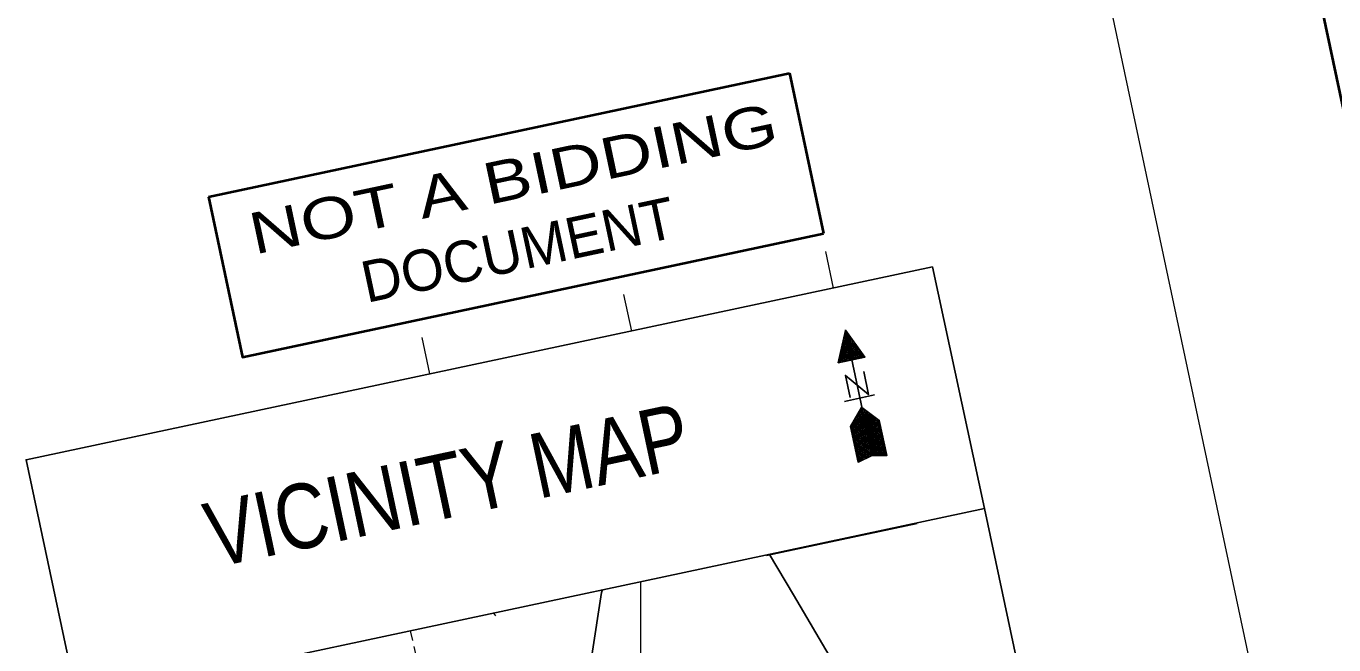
# Model space of a CAD drawing. Extents: x 2357218 to 2371708, y 6973728 to 6980157.
# Drawn here: x 2357218 to 2357852, y 6974891 to 6975190 of the extents above; entities that cross this region are included whole.
import ezdxf
from ezdxf.enums import TextEntityAlignment as Align

# ---------------------------------------------------------------- set-up
doc = ezdxf.new("R2010")
doc.units = 0
doc.header["$LTSCALE"] = 2
doc.linetypes.add('MEDIUM_DASHED', pattern=[4.5, 3, -1.5])
for name, color, linetype, lineweight in [('44', 7, 'Continuous', 13), ('62', 7, 'Continuous', 13), ('63', 7, 'Continuous', 13)]:
    doc.layers.add(name, color=color, linetype=linetype, lineweight=lineweight)

msp = doc.modelspace()

# ---------------------------------------------------------------- linework, layer by layer
at = {"layer": '44'}
msp.add_line((2358039.664, 6973807.926), (2357291.149, 6977329.415), dxfattribs=at)
at = {"layer": '44', "lineweight": 40}
msp.add_lwpolyline([(2358116.692, 6973926.537), (2357409.76, 6977252.388), (2370517.53, 6980038.532)], dxfattribs=at)
at = {"layer": '62', "lineweight": 40}
for p, q in [((2357306.373, 6975107.636), (2357588.056, 6975167.509)), ((2357588.056, 6975167.509), (2357604.573, 6975089.803))]:
    msp.add_line(p, q, dxfattribs=at)
at = {"layer": '62'}
for p, q in [((2357605.468, 6975081.127), (2357609.235, 6975063.405)), ((2357507.65, 6975060.335), (2357511.417, 6975042.612)), ((2357614.522, 6975039.726), (2357617.208, 6975040.297)), ((2357614.683, 6975040.382), (2357616.819, 6975040.837)), ((2357617.301, 6975028.402), (2357614.717, 6975040.55)), ((2357614.833, 6975041.083), (2357616.418, 6975041.417)), ((2357614.994, 6975041.737), (2357616.006, 6975041.951)), ((2357617.915, 6975028.532), (2357615.052, 6975042.001)), ((2357615.149, 6975042.414), (2357615.611, 6975042.512)), ((2357618.532, 6975028.663), (2357615.575, 6975042.572)), ((2357619.147, 6975028.797), (2357616.491, 6975041.295)), ((2357409.831, 6975039.543), (2357413.598, 6975021.82)), ((2357612.86, 6975032.288), (2357621.62, 6975034.152)), ((2357613.036, 6975032.972), (2357621.225, 6975034.712)), ((2357613.171, 6975033.644), (2357620.83, 6975035.272)), ((2357613.325, 6975034.321), (2357620.435, 6975035.833)), ((2357614.832, 6975027.877), (2357613.396, 6975034.635)), ((2357613.48, 6975034.998), (2357620.018, 6975036.388)), ((2357613.614, 6975035.669), (2357619.623, 6975036.948)), ((2357615.448, 6975028.008), (2357613.722, 6975036.129)), ((2357613.768, 6975036.346), (2357619.206, 6975037.504)), ((2357613.922, 6975037.025), (2357618.811, 6975038.064)), ((2357616.064, 6975028.14), (2357614.053, 6975037.602)), ((2357614.079, 6975037.7), (2357618.393, 6975038.619)), ((2357614.239, 6975038.355), (2357618.002, 6975039.157)), ((2357614.388, 6975039.056), (2357617.604, 6975039.739)), ((2357616.681, 6975028.271), (2357614.388, 6975039.056)), ((2357619.743, 6975028.921), (2357617.385, 6975040.014)), ((2357620.38, 6975029.057), (2357618.317, 6975038.763)), ((2357620.996, 6975029.188), (2357619.233, 6975037.486)), ((2357621.589, 6975029.313), (2357620.122, 6975036.226)), ((2357622.229, 6975029.449), (2357621.059, 6975034.951)), ((2357611.814, 6975027.58), (2357624.426, 6975030.263)), ((2357611.973, 6975028.235), (2357624.035, 6975030.801)), ((2357612.367, 6975027.354), (2357612.075, 6975028.739)), ((2357612.127, 6975028.914), (2357623.64, 6975031.361)), ((2357612.258, 6975029.609), (2357623.219, 6975031.938)), ((2357612.983, 6975027.485), (2357612.401, 6975030.236)), ((2357612.415, 6975030.264), (2357622.827, 6975032.475)), ((2357612.572, 6975030.939), (2357622.432, 6975033.035)), ((2357612.705, 6975031.611), (2357622.015, 6975033.592)), ((2357613.601, 6975027.616), (2357612.734, 6975031.688)), ((2357614.216, 6975027.747), (2357613.06, 6975033.183)), ((2357622.823, 6975029.577), (2357621.953, 6975033.671)), ((2357623.44, 6975029.707), (2357622.864, 6975032.415)), ((2357624.077, 6975029.843), (2357623.801, 6975031.142)), ((2357611.772, 6975027.228), (2357611.758, 6975027.294)), ((2357620.457, 6975001.098), (2357627.168, 6975002.527)), ((2357620.875, 6975001.833), (2357626.488, 6975003.026)), ((2357621.311, 6975002.59), (2357625.824, 6975003.552)), ((2357626.004, 6974981.388), (2357621.445, 6975002.827)), ((2357621.736, 6975003.302), (2357625.148, 6975004.03)), ((2357626.585, 6974981.674), (2357621.914, 6975003.641)), ((2357622.155, 6975004.037), (2357624.489, 6975004.532)), ((2357627.177, 6974981.937), (2357622.391, 6975004.456)), ((2357622.576, 6975004.769), (2357623.808, 6975005.033)), ((2357627.759, 6974982.222), (2357622.861, 6975005.267)), ((2357628.38, 6974982.331), (2357623.505, 6975005.267)), ((2357629.024, 6974982.33), (2357624.271, 6975004.692)), ((2357629.647, 6974982.323), (2357625.015, 6975004.116)), ((2357630.319, 6974982.306), (2357625.798, 6975003.569)), ((2357630.959, 6974982.327), (2357626.564, 6975002.995)), ((2357631.585, 6974982.298), (2357627.303, 6975002.44)), ((2357621.331, 6974979.131), (2357617.675, 6974996.321)), ((2357617.715, 6974996.029), (2357631.649, 6974998.993)), ((2357617.845, 6974995.415), (2357631.78, 6974998.377)), ((2357617.914, 6974996.716), (2357631.207, 6974999.543)), ((2357617.976, 6974994.799), (2357631.909, 6974997.76)), ((2357618.108, 6974994.18), (2357632.04, 6974997.142)), ((2357621.934, 6974979.419), (2357618.168, 6974997.14)), ((2357618.239, 6974993.564), (2357632.172, 6974996.525)), ((2357618.316, 6974997.425), (2357630.529, 6975000.021)), ((2357618.37, 6974992.946), (2357632.305, 6974995.909)), ((2357622.498, 6974979.701), (2357618.618, 6974997.947)), ((2357618.751, 6974998.184), (2357629.867, 6975000.547)), ((2357623.08, 6974979.984), (2357619.087, 6974998.761)), ((2357619.17, 6974998.917), (2357629.186, 6975001.046)), ((2357623.663, 6974980.27), (2357619.56, 6974999.573)), ((2357619.617, 6974999.634), (2357628.511, 6975001.522)), ((2357620.031, 6975000.388), (2357627.847, 6975002.047)), ((2357624.252, 6974980.532), (2357620.031, 6975000.388)), ((2357624.835, 6974980.817), (2357620.502, 6975001.202)), ((2357625.418, 6974981.103), (2357620.973, 6975002.015)), ((2357632.248, 6974982.303), (2357628.091, 6975001.871)), ((2357632.873, 6974982.297), (2357628.835, 6975001.293)), ((2357633.517, 6974982.298), (2357629.601, 6975000.72)), ((2357634.183, 6974982.299), (2357630.389, 6975000.151)), ((2357634.806, 6974982.295), (2357631.128, 6974999.596)), ((2357618.501, 6974992.33), (2357632.434, 6974995.292)), ((2357618.632, 6974991.715), (2357632.565, 6974994.675)), ((2357618.761, 6974991.098), (2357632.696, 6974994.06)), ((2357618.892, 6974990.481), (2357632.825, 6974993.443)), ((2357619.027, 6974989.866), (2357632.958, 6974992.826)), ((2357619.153, 6974989.273), (2357633.084, 6974992.232)), ((2357619.287, 6974988.633), (2357633.221, 6974991.595)), ((2357619.418, 6974988.017), (2357633.35, 6974990.979)), ((2357619.546, 6974987.422), (2357633.479, 6974990.385)), ((2357619.68, 6974986.785), (2357633.612, 6974989.746)), ((2357619.806, 6974986.191), (2357633.741, 6974989.153)), ((2357619.937, 6974985.573), (2357633.87, 6974988.536)), ((2357620.073, 6974984.936), (2357634.005, 6974987.898)), ((2357620.199, 6974984.342), (2357634.132, 6974987.304)), ((2357620.33, 6974983.724), (2357634.263, 6974986.688)), ((2357620.463, 6974983.11), (2357634.394, 6974986.069)), ((2357620.592, 6974982.494), (2357634.526, 6974985.456)), ((2357620.723, 6974981.875), (2357634.655, 6974984.839)), ((2357620.854, 6974981.259), (2357634.786, 6974984.223)), ((2357628.886, 6974982.324), (2357634.917, 6974983.606)), ((2357620.983, 6974980.645), (2357627.237, 6974981.974)), ((2357621.116, 6974980.027), (2357624.835, 6974980.817)), ((2357621.249, 6974979.413), (2357622.435, 6974979.663)), ((2357631.858, 6974982.312), (2357635.051, 6974982.989)), ((2357634.782, 6974982.29), (2357635.18, 6974982.372)), ((2357576.9, 6974933.822), (2357649.886, 6974949.336)), ((2357444.571, 6974905.924), (2357445.581, 6974904.529))]:
    msp.add_line(p, q, dxfattribs=at)
at = {"layer": '62', "lineweight": 25}
for p, q in [((2357615.19, 6975043.203), (2357628.184, 6974982.059)), ((2357614.713, 6975008.526), (2357629.33, 6975011.633)), ((2357242.867, 6974863.05), (2357682.634, 6974956.528))]:
    msp.add_line(p, q, dxfattribs=at)
at = {"layer": '62', "linetype": 'MEDIUM_DASHED'}
msp.add_line((2357425, 6974804.799), (2357404.314, 6974897.367), dxfattribs=at)
at = {"layer": '62', "lineweight": 40}
msp.add_lwpolyline([(2357306.373, 6975107.636), (2357322.89, 6975029.931), (2357604.573, 6975089.803)], dxfattribs=at)
at = {"layer": '62', "lineweight": 25}
for points in [[(2357242.867, 6974863.05), (2357217.961, 6974980.235), (2357657.397, 6975073.642), (2357682.634, 6974956.528)], [(2357615.246, 6975042.919), (2357611.729, 6975027.218), (2357624.649, 6975029.964), (2357615.22, 6975043.05)], [(2357617.427, 6975010.369), (2357615.14, 6975021.13), (2357626.447, 6975011.873), (2357624.076, 6975023.032)], [(2357622.999, 6975005.48), (2357617.659, 6974996.293), (2357621.308, 6974979.126), (2357627.987, 6974982.34), (2357635.2, 6974982.286), (2357631.591, 6974999.255), (2357623.206, 6975005.479)], [(2357242.867, 6974863.05), (2357339.603, 6974407.945), (2357779.37, 6974501.42), (2357682.634, 6974956.528)], [(2357578.331, 6974934.355), (2357589.96, 6974914.697), (2357608.93, 6974882.704), (2357634.925, 6974864.627), (2357663.018, 6974846.971), (2357666.063, 6974842.928)], [(2357497.44, 6974917.163), (2357496.955, 6974915.862), (2357492.272, 6974885.305), (2357482.941, 6974855.925), (2357475.827, 6974835.503), (2357471.545, 6974803.052)]]:
    msp.add_lwpolyline(points, dxfattribs=at)
at = {"layer": '62'}
msp.add_lwpolyline([(2357500.903, 6974797.836), (2357515.999, 6974857.775), (2357516.041, 6974920.68)], dxfattribs=at)
at = {"layer": '63', "lineweight": 40}
for p, q in [((2357306.373, 6975107.636), (2357588.056, 6975167.509)), ((2357588.056, 6975167.509), (2357604.573, 6975089.803))]:
    msp.add_line(p, q, dxfattribs=at)
at = {"layer": '63'}
for p, q in [((2357605.468, 6975081.127), (2357609.235, 6975063.405)), ((2357507.65, 6975060.335), (2357511.417, 6975042.612)), ((2357614.522, 6975039.726), (2357617.208, 6975040.297)), ((2357614.683, 6975040.382), (2357616.819, 6975040.837)), ((2357617.301, 6975028.402), (2357614.717, 6975040.55)), ((2357614.833, 6975041.083), (2357616.418, 6975041.417)), ((2357614.994, 6975041.737), (2357616.006, 6975041.951)), ((2357617.915, 6975028.532), (2357615.052, 6975042.001)), ((2357615.149, 6975042.414), (2357615.611, 6975042.512)), ((2357618.532, 6975028.663), (2357615.575, 6975042.572)), ((2357619.147, 6975028.797), (2357616.491, 6975041.295)), ((2357409.831, 6975039.543), (2357413.598, 6975021.82)), ((2357612.86, 6975032.288), (2357621.62, 6975034.152)), ((2357613.036, 6975032.972), (2357621.225, 6975034.712)), ((2357613.171, 6975033.644), (2357620.83, 6975035.272)), ((2357613.325, 6975034.321), (2357620.435, 6975035.833)), ((2357614.832, 6975027.877), (2357613.396, 6975034.635)), ((2357613.48, 6975034.998), (2357620.018, 6975036.388)), ((2357613.614, 6975035.669), (2357619.623, 6975036.948)), ((2357615.448, 6975028.008), (2357613.722, 6975036.129)), ((2357613.768, 6975036.346), (2357619.206, 6975037.504)), ((2357613.922, 6975037.025), (2357618.811, 6975038.064)), ((2357616.064, 6975028.14), (2357614.053, 6975037.602)), ((2357614.079, 6975037.7), (2357618.393, 6975038.619)), ((2357614.239, 6975038.355), (2357618.002, 6975039.157)), ((2357614.388, 6975039.056), (2357617.604, 6975039.739)), ((2357616.681, 6975028.271), (2357614.388, 6975039.056)), ((2357619.743, 6975028.921), (2357617.385, 6975040.014)), ((2357620.38, 6975029.057), (2357618.317, 6975038.763)), ((2357620.996, 6975029.188), (2357619.233, 6975037.486)), ((2357621.589, 6975029.313), (2357620.122, 6975036.226)), ((2357622.229, 6975029.449), (2357621.059, 6975034.951)), ((2357611.814, 6975027.58), (2357624.426, 6975030.263)), ((2357611.973, 6975028.235), (2357624.035, 6975030.801)), ((2357612.367, 6975027.354), (2357612.075, 6975028.739)), ((2357612.127, 6975028.914), (2357623.64, 6975031.361)), ((2357612.258, 6975029.609), (2357623.219, 6975031.938)), ((2357612.983, 6975027.485), (2357612.401, 6975030.236)), ((2357612.415, 6975030.264), (2357622.827, 6975032.475)), ((2357612.572, 6975030.939), (2357622.432, 6975033.035)), ((2357612.705, 6975031.611), (2357622.015, 6975033.592)), ((2357613.601, 6975027.616), (2357612.734, 6975031.688)), ((2357614.216, 6975027.747), (2357613.06, 6975033.183)), ((2357622.823, 6975029.577), (2357621.953, 6975033.671)), ((2357623.44, 6975029.707), (2357622.864, 6975032.415)), ((2357624.077, 6975029.843), (2357623.801, 6975031.142)), ((2357611.772, 6975027.228), (2357611.758, 6975027.294)), ((2357620.457, 6975001.098), (2357627.168, 6975002.527)), ((2357620.875, 6975001.833), (2357626.488, 6975003.026)), ((2357621.311, 6975002.59), (2357625.824, 6975003.552)), ((2357626.004, 6974981.388), (2357621.445, 6975002.827)), ((2357621.736, 6975003.302), (2357625.148, 6975004.03)), ((2357626.585, 6974981.674), (2357621.914, 6975003.641)), ((2357622.155, 6975004.037), (2357624.489, 6975004.532)), ((2357627.177, 6974981.937), (2357622.391, 6975004.456)), ((2357622.576, 6975004.769), (2357623.808, 6975005.033)), ((2357627.759, 6974982.222), (2357622.861, 6975005.267)), ((2357628.38, 6974982.331), (2357623.505, 6975005.267)), ((2357629.024, 6974982.33), (2357624.271, 6975004.692)), ((2357629.647, 6974982.323), (2357625.015, 6975004.116)), ((2357630.319, 6974982.306), (2357625.798, 6975003.569)), ((2357630.959, 6974982.327), (2357626.564, 6975002.995)), ((2357631.585, 6974982.298), (2357627.303, 6975002.44)), ((2357621.331, 6974979.131), (2357617.675, 6974996.321)), ((2357617.715, 6974996.029), (2357631.649, 6974998.993)), ((2357617.845, 6974995.415), (2357631.78, 6974998.377)), ((2357617.914, 6974996.716), (2357631.207, 6974999.543)), ((2357617.976, 6974994.799), (2357631.909, 6974997.76)), ((2357618.108, 6974994.18), (2357632.04, 6974997.142)), ((2357621.934, 6974979.419), (2357618.168, 6974997.14)), ((2357618.239, 6974993.564), (2357632.172, 6974996.525)), ((2357618.316, 6974997.425), (2357630.529, 6975000.021)), ((2357618.37, 6974992.946), (2357632.305, 6974995.909)), ((2357622.498, 6974979.701), (2357618.618, 6974997.947)), ((2357618.751, 6974998.184), (2357629.867, 6975000.547)), ((2357623.08, 6974979.984), (2357619.087, 6974998.761)), ((2357619.17, 6974998.917), (2357629.186, 6975001.046)), ((2357623.663, 6974980.27), (2357619.56, 6974999.573)), ((2357619.617, 6974999.634), (2357628.511, 6975001.522)), ((2357620.031, 6975000.388), (2357627.847, 6975002.047)), ((2357624.252, 6974980.532), (2357620.031, 6975000.388)), ((2357624.835, 6974980.817), (2357620.502, 6975001.202)), ((2357625.418, 6974981.103), (2357620.973, 6975002.015)), ((2357632.248, 6974982.303), (2357628.091, 6975001.871)), ((2357632.873, 6974982.297), (2357628.835, 6975001.293)), ((2357633.517, 6974982.298), (2357629.601, 6975000.72)), ((2357634.183, 6974982.299), (2357630.389, 6975000.151)), ((2357634.806, 6974982.295), (2357631.128, 6974999.596)), ((2357618.501, 6974992.33), (2357632.434, 6974995.292)), ((2357618.632, 6974991.715), (2357632.565, 6974994.675)), ((2357618.761, 6974991.098), (2357632.696, 6974994.06)), ((2357618.892, 6974990.481), (2357632.825, 6974993.443)), ((2357619.027, 6974989.866), (2357632.958, 6974992.826)), ((2357619.153, 6974989.273), (2357633.084, 6974992.232)), ((2357619.287, 6974988.633), (2357633.221, 6974991.595)), ((2357619.418, 6974988.017), (2357633.35, 6974990.979)), ((2357619.546, 6974987.422), (2357633.479, 6974990.385)), ((2357619.68, 6974986.785), (2357633.612, 6974989.746)), ((2357619.806, 6974986.191), (2357633.741, 6974989.153)), ((2357619.937, 6974985.573), (2357633.87, 6974988.536)), ((2357620.073, 6974984.936), (2357634.005, 6974987.898)), ((2357620.199, 6974984.342), (2357634.132, 6974987.304)), ((2357620.33, 6974983.724), (2357634.263, 6974986.688)), ((2357620.463, 6974983.11), (2357634.394, 6974986.069)), ((2357620.592, 6974982.494), (2357634.526, 6974985.456)), ((2357620.723, 6974981.875), (2357634.655, 6974984.839)), ((2357620.854, 6974981.259), (2357634.786, 6974984.223)), ((2357628.886, 6974982.324), (2357634.917, 6974983.606)), ((2357620.983, 6974980.645), (2357627.237, 6974981.974)), ((2357621.116, 6974980.027), (2357624.835, 6974980.817)), ((2357621.249, 6974979.413), (2357622.435, 6974979.663)), ((2357631.858, 6974982.312), (2357635.051, 6974982.989)), ((2357634.782, 6974982.29), (2357635.18, 6974982.372)), ((2357576.9, 6974933.822), (2357649.886, 6974949.336)), ((2357444.571, 6974905.924), (2357445.581, 6974904.529))]:
    msp.add_line(p, q, dxfattribs=at)
at = {"layer": '63', "lineweight": 25}
for p, q in [((2357615.19, 6975043.203), (2357628.184, 6974982.059)), ((2357614.713, 6975008.526), (2357629.33, 6975011.633)), ((2357242.867, 6974863.05), (2357682.634, 6974956.528))]:
    msp.add_line(p, q, dxfattribs=at)
at = {"layer": '63', "linetype": 'MEDIUM_DASHED'}
msp.add_line((2357425, 6974804.799), (2357404.314, 6974897.367), dxfattribs=at)
at = {"layer": '63', "lineweight": 40}
msp.add_lwpolyline([(2357306.373, 6975107.636), (2357322.89, 6975029.931), (2357604.573, 6975089.803)], dxfattribs=at)
at = {"layer": '63', "lineweight": 25}
for points in [[(2357242.867, 6974863.05), (2357217.961, 6974980.235), (2357657.397, 6975073.642), (2357682.634, 6974956.528)], [(2357615.246, 6975042.919), (2357611.729, 6975027.218), (2357624.649, 6975029.964), (2357615.22, 6975043.05)], [(2357617.427, 6975010.369), (2357615.14, 6975021.13), (2357626.447, 6975011.873), (2357624.076, 6975023.032)], [(2357622.999, 6975005.48), (2357617.659, 6974996.293), (2357621.308, 6974979.126), (2357627.987, 6974982.34), (2357635.2, 6974982.286), (2357631.591, 6974999.255), (2357623.206, 6975005.479)], [(2357242.867, 6974863.05), (2357339.603, 6974407.945), (2357779.37, 6974501.42), (2357682.634, 6974956.528)], [(2357578.331, 6974934.355), (2357589.96, 6974914.697), (2357608.93, 6974882.704), (2357634.925, 6974864.627), (2357663.018, 6974846.971), (2357666.063, 6974842.928)], [(2357497.44, 6974917.163), (2357496.955, 6974915.862), (2357492.272, 6974885.305), (2357482.941, 6974855.925), (2357475.827, 6974835.503), (2357471.545, 6974803.052)]]:
    msp.add_lwpolyline(points, dxfattribs=at)
at = {"layer": '63'}
msp.add_lwpolyline([(2357500.903, 6974797.836), (2357515.999, 6974857.775), (2357516.041, 6974920.68)], dxfattribs=at)

# ---------------------------------------------------------------- texts
at = {"layer": '62', "width": 1.3}
msp.add_text('NOT A BIDDING', height=20, rotation=12, dxfattribs=at).set_placement((2357456.249, 6975106.709), align=Align.CENTER)
at = {"layer": '62'}
msp.add_text('DOCUMENT', height=20, rotation=12, dxfattribs=at).set_placement((2357458.606, 6975072.243), align=Align.CENTER)
at = {"layer": '62', "width": 0.85}
msp.add_text('VICINITY MAP', height=31.45, rotation=12, dxfattribs=at).set_placement((2357308.943, 6974927.754))
at = {"layer": '63', "width": 1.3}
msp.add_text('NOT A BIDDING', height=20, rotation=12, dxfattribs=at).set_placement((2357456.249, 6975106.709), align=Align.CENTER)
at = {"layer": '63'}
msp.add_text('DOCUMENT', height=20, rotation=12, dxfattribs=at).set_placement((2357458.606, 6975072.243), align=Align.CENTER)
at = {"layer": '63', "width": 0.85}
msp.add_text('VICINITY MAP', height=31.45, rotation=12, dxfattribs=at).set_placement((2357308.943, 6974927.754))

doc.saveas('drawing.dxf')
